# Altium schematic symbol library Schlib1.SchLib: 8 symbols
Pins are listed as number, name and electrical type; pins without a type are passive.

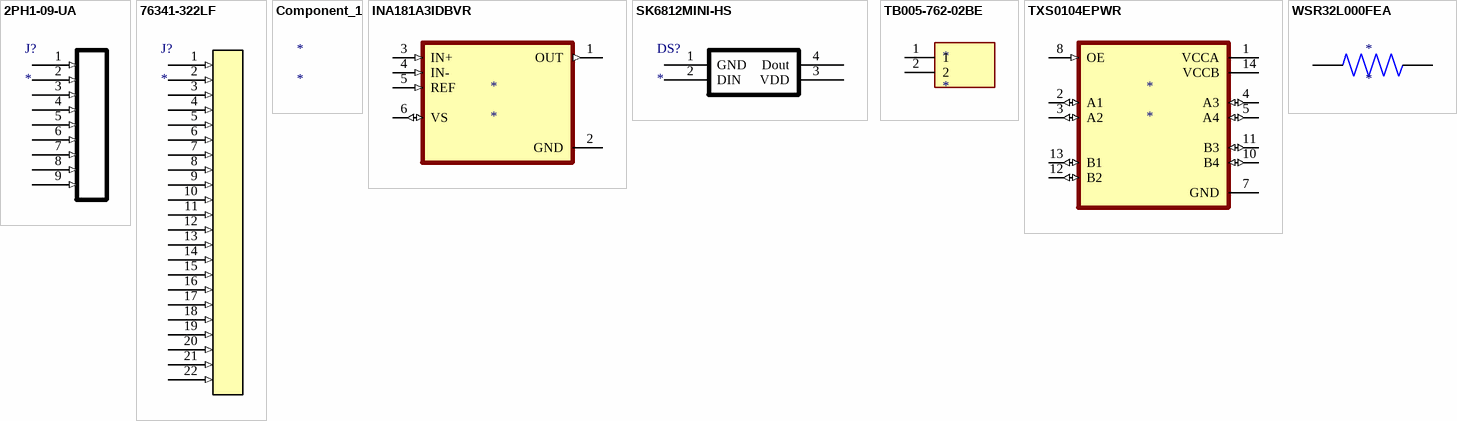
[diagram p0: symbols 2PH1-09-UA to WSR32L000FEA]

## 2PH1-09-UA
designator J?
Conn Unshrouded Header HDR 9 POS 2mm Solder ST Thru-Hole; Manufacturer: Adam Tech; Manufacturer Part Number: 2PH1-09-UA; Contact Resistance: 20mΩ; Current Rating: 1A; Insulation Resistance: 5GΩ
footprint 2AMPHENOL_76341-322LF - duplicate
pins: 1 (in), 2 (in), 3 (in), 4 (in), 5 (in), 6 (in), 7 (in), 8 (in), 9 (in)

## 76341-322LF
designator J?
FCI 2.54mm 22 Way 1 Row Straight IDC Connector Through Hole Board to Board; Manufacturer: Amphenol ICC / FCI; Manufacturer Part Number: 76341-322LF; Manufacturer Series: 76341; Connector Type: BOARD CONNECTOR; Option: General Purpose; Body/Shell Style: RECEPTACLE; Contact Pattern: RECTANGULAR; Contact Resistance: 20mR; Contact Style: SQ PIN-SKT; Dielectric Withstanding Voltage (AC): 1.4kV; Filter Feature: No; Insulation Resistance: 1GR; Number Of Connectors: 1; Polarization Key: POLARIZED HOUSING; Rated Current (Signal): 2A; Number of Contacts: 22; Body Breadth: 0.1inch; Body Depth: 0.276inch; Body Length: 2.12inch; Mounting Option 1: LOCKING; Plating Thickness: 30uin; Reference Standard: UL; Reliability: COMMERCIAL
footprint AMPHENOL_76341-322LF
pins: 1 (in), 2 (in), 3 (in), 4 (in), 5 (in), 6 (in), 7 (in), 8 (in), 9 (in), 10 (in), 11 (in), 12 (in), 13 (in), 14 (in), 15 (in), 16 (in), 17 (in), 18 (in), 19 (in), 20 (in), 21 (in), 22 (in)

## Component_1
designator *

## INA181A3IDBVR
designator *
Operational Amplifier, 1 Func, 500uV Offset-Max, PDSO6; Manufacturer: Texas Instruments; Manufacturer Part Number: INA181A3IDBVR; Package Body Material: Plastic; Average Bias Current-Max (IIB): 75uA; Common-mode Reject Ratio-Nom: 100dB; Channels: 1; Slew Rate: 2V/µs; Supply Voltage Limit-Max: 5.5V; Nominal Supply Voltage: 5V; Unity Gain BW-Nom: 350kHz
footprint SOT95P280X145-6N
pins: 1 OUT (out), 2 GND (power), 3 IN+ (in), 4 IN- (in), 5 REF (in), 6 VS (io)

## SK6812MINI-HS
designator DS?
footprint LED
pins: 1 GND, 2 DIN, 3 VDD, 4 Dout

## TB005-762-02BE
designator *
Barrier Strip Terminal Block; Manufacturer: Same Sky; Manufacturer Part Number: TB005-762-02BE
footprint CUI_TB005-762-02BE
pins: 1, 2

## TXS0104EPWR
designator *
Four-bit bidirectional voltage-level shifter for open-drain and push-pull applications 14-TSSOP -40 to 85; Manufacturer: Texas Instruments; Manufacturer Part Number: TXS0104EPWR; Manufacturer Lifecycle Status: ACTIVE; Data Rate: 24mbps; High Level Output Current: -20µA; Logic Function: Translator; Low Level Output Current: 1mA; Max Junction Temperature (Tj): 150°C; Max Supply Voltage: 5.5V; Min Supply Voltage: 1.65V; Number of Bits: 4; Output Current: 50mA; Propagation Delay: 4.6ns; Quiescent Current: 14.4µA; Turn-On Delay Time: 260ns
footprint SOP65P640X120-14N
pins: 1 VCCA (power), 2 A1 (io), 3 A2 (io), 4 A3 (io), 5 A4 (io), 7 GND (power), 8 OE (in), 10 B4 (io), 11 B3 (io), 12 B2 (io), 13 B1 (io), 14 VCCB (power)

## WSR32L000FEA
designator *
Fixed Resistor, Metal Strip, 3W, 0.002ohm, 0.077V, 1% +/-Tol, 600ppm/Cel, Surface Mount, 4527; Manufacturer: Vishay Dale; Manufacturer Part Number: WSR32L000FEA; Rated Temperature: 70°C; Value: 2mR; Temperature Coefficient (ppm/Cel): -600,600; Package Height: 2.41mm; Package Length: 11.56mm; Package Width: 6.98mm; Reference Standard: AEC-Q200
footprint RESM11569X253N
pins: 1, 2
